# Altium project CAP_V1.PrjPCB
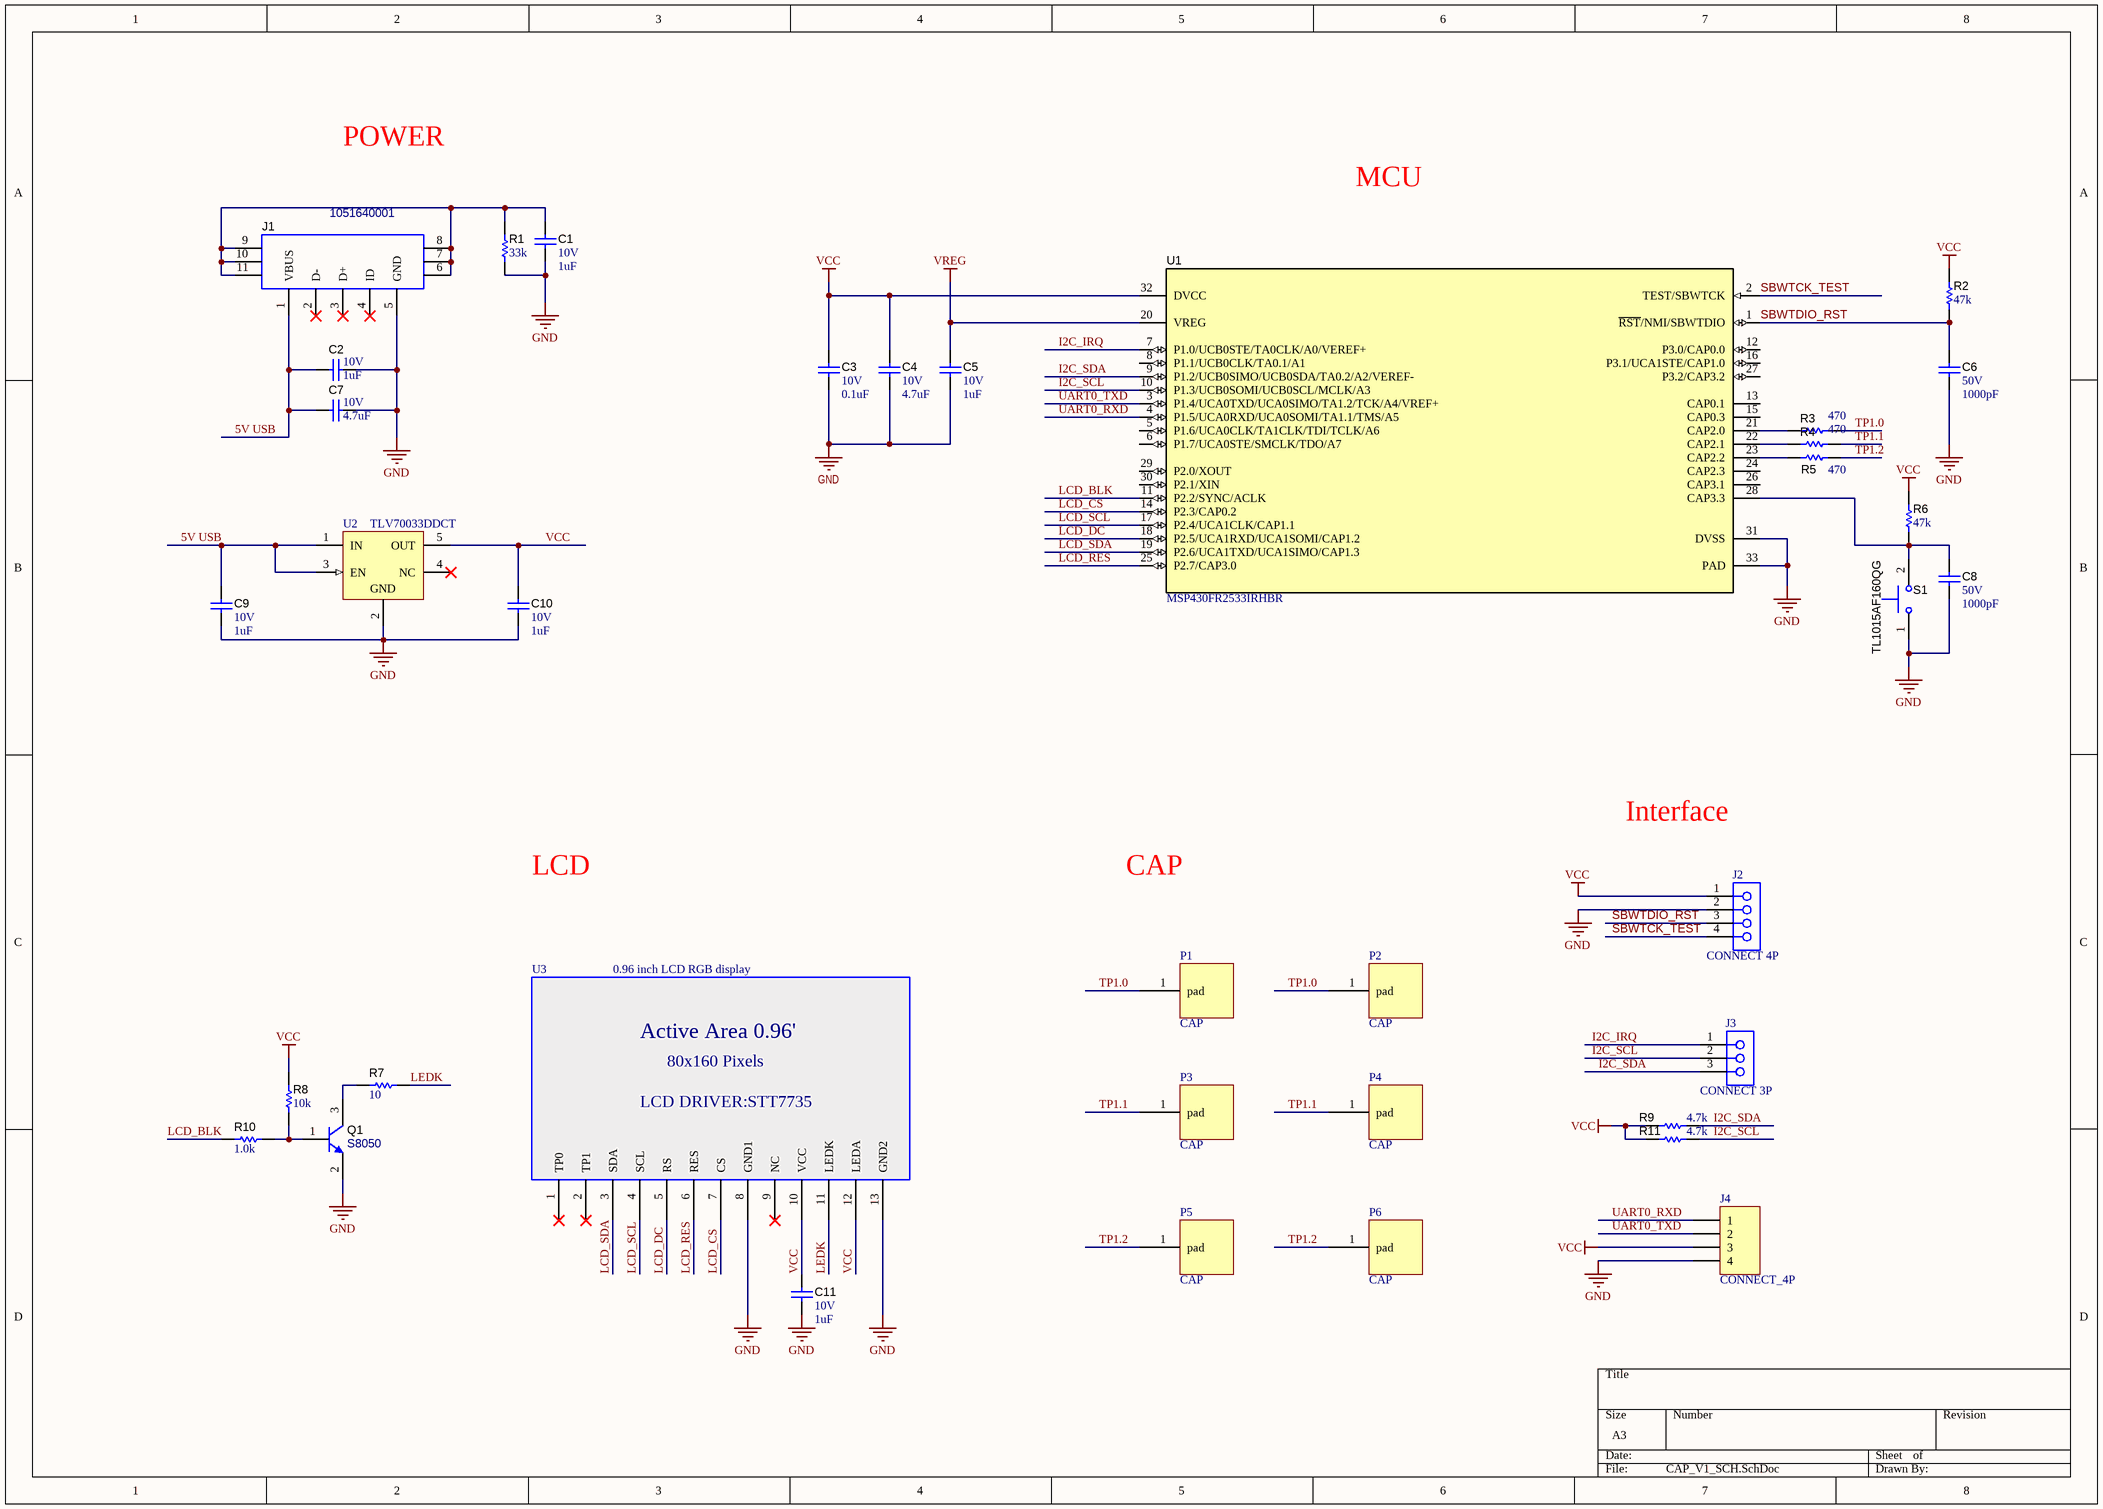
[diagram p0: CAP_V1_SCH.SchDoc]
1 sheet, 37 parts. Net scope: global (net labels, ports and power ports of the same name join across sheets).
Board file: CAP_V1_PCB.PcbDoc

## Sheet CAP_V1_SCH.SchDoc
size A3

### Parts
C1  VDC_V: 10V  ValueDisplayed: 1uF  [0603]  (hidden comment: CGB3B1X5R1A475K055AC)
C2  VDC_V: 10V  ValueDisplayed: 1uF  [0603]  (hidden comment: CGB3B1X5R1A475K055AC)
C3  VDC_V: 10V  ValueDisplayed: 0.1uF  [0603]  (hidden comment: CGB3B1X5R1A475K055AC)
C4  VDC_V: 10V  ValueDisplayed: 4.7uF  [0603]  (hidden comment: CGB3B1X5R1A475K055AC)
C5  VDC_V: 10V  ValueDisplayed: 1uF  [0603]  (hidden comment: C1608X5R1A105K080AC)
C6  VDC_V: 50V  ValueDisplayed: 1000pF  [0402]  (hidden comment: GRM155R61H102KA01D)
C7  VDC_V: 10V  ValueDisplayed: 4.7uF  [0603]  (hidden comment: CGB3B1X5R1A475K055AC)
C8  VDC_V: 50V  ValueDisplayed: 1000pF  [0402]  (hidden comment: GRM155R61H102KA01D)
C9  VDC_V: 10V  ValueDisplayed: 1uF  [0603]  (hidden comment: CGB3B1X5R1A475K055AC)
C10  VDC_V: 10V  ValueDisplayed: 1uF  [0603]  (hidden comment: CGB3B1X5R1A475K055AC)
C11  VDC_V: 10V  ValueDisplayed: 1uF  [0603]  (hidden comment: CGB3B1X5R1A475K055AC)
J1  1051640001  [Molex_1051640001]
J2  CONNECT 4P  [HDR1X4]
J3  CONNECT 3P  [HDR1X3]
J4  CONNECT_4P  [HDR1X4]
P1  CAP  [PCBComponent_1]
P2  CAP  [PCBComponent_1]
P3  CAP  [PCBComponent_1]
P4  CAP  [PCBComponent_1]
P5  CAP  [PCBComponent_1]
P6  CAP  [PCBComponent_1]
Q1  S8050  [SOT-23]
R1  ValueDisplayed: 33k  [0402]  (hidden comment: CRCW040247K0JNED)
R2  ValueDisplayed: 47k  [0402]  (hidden comment: CRCW040247K0JNED)
R3  ValueDisplayed: 470  [0402]  (hidden comment: CRCW040247K0JNED)
R4  ValueDisplayed: 470  [0402]  (hidden comment: CRCW040247K0JNED)
R5  ValueDisplayed: 470  [0402]  (hidden comment: CRCW040247K0JNED)
R6  ValueDisplayed: 47k  [0402]  (hidden comment: CRCW040247K0JNED)
R7  ValueDisplayed: 10  [0402L]  (hidden comment: CRCW040210R0JNED)
R8  ValueDisplayed: 10k  [0402L]  (hidden comment: CRCW040210K0JNED)
R9  ValueDisplayed: 4.7k  [0402]  (hidden comment: CRCW04024K70JNED)
R10  ValueDisplayed: 1.0k  [0402L]  (hidden comment: CRCW04021K00JNED)
R11  ValueDisplayed: 4.7k  [0402]  (hidden comment: CRCW04024K70JNED)
S1  TL1015AF160QG  [SW_TL1015AF160QG]
U1  MSP430FR2533IRHBR  [RHB0032E_NV]
U2  TLV70033DDCT  [DDC0005A_N]
U3  0.96 inch LCD RGB display  [GMT096-01]

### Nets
GND: C1.2 C2.2 C3.2 C4.2 C5.2 C6.2 C7.2 C8.2 C9.2 C10.2 C11.2 J1.5(GND) J2.2 J4.4 Q1.2(E) R1.1 S1.1 U1.31(DVSS) U1.33(PAD) U2.2(GND) U3.8(GND1) U3.13(GND2)
VCC: C3.1 C4.1 C10.1 C11.1 J2.1 J4.3 R2.2 R6.2 R8.2 R9.1 R11.1 U1.32(DVCC) U2.5(OUT) U3.10(VCC) U3.12(LEDA)
VREG: C5.1 U1.20(VREG)
5V USB: C2.1 C7.1 C9.1 J1.1(VBUS) U2.1(IN) U2.3(EN)
I2C_IRQ: J3.1 U1.7(P1.0/UCB0STE/TA0CLK/A0/VEREF+)
I2C_SCL: J3.2 R11.2 U1.10(P1.3/UCB0SOMI/UCB0SCL/MCLK/A3)
I2C_SDA: J3.3 R9.2 U1.9(P1.2/UCB0SIMO/UCB0SDA/TA0.2/A2/VEREF-)
LCD_BLK: R10.1 U1.11(P2.2/SYNC/ACLK)
LCD_CS: U1.14(P2.3/CAP0.2) U3.7(CS)
LCD_DC: U1.18(P2.5/UCA1RXD/UCA1SOMI/CAP1.2) U3.5(RS)
LCD_RES: U1.25(P2.7/CAP3.0) U3.6(RES)
LCD_SCL: U1.17(P2.4/UCA1CLK/CAP1.1) U3.4(SCL)
LCD_SDA: U1.19(P2.6/UCA1TXD/UCA1SIMO/CAP1.3) U3.3(SDA)
LEDK: R7.2 U3.11(LEDK)
SBWTCK_TEST: J2.4 U1.2(TEST/SBWTCK)
SBWTDIO_RST: C6.1 J2.3 R2.1 U1.1(~{RST}/NMI/SBWTDIO)
TP1.0: P1.1(pad) P2.1(pad) R3.1
TP1.1: P3.1(pad) P4.1(pad) R4.1
TP1.2: P5.1(pad) P6.1(pad) R5.1
UART0_RXD: J4.1 U1.4(P1.5/UCA0RXD/UCA0SOMI/TA1.1/TMS/A5)
UART0_TXD: J4.2 U1.3(P1.4/UCA0TXD/UCA0SIMO/TA1.2/TCK/A4/VREF+)
NetC1_1: C1.1 J1.6 J1.7 J1.8 J1.9 J1.10 J1.11 R1.2
NetC8_1: C8.1 R6.1 S1.2 U1.28(CAP3.3)
NetQ1_1: Q1.1(B) R8.1 R10.2
NetQ1_3: Q1.3(C) R7.1
NetR3_2: R3.2 U1.21(CAP2.0)
NetR4_2: R4.2 U1.22(CAP2.1)
NetR5_2: R5.2 U1.23(CAP2.2)

Not connected (* = marked no-connect by the designer): J1 2(D-)* 3(D+)* 4(ID)*; U1 5(P1.6/UCA0CLK/TA1CLK/TDI/TCLK/A6) 6(P1.7/UCA0STE/SMCLK/TDO/A7) 8(P1.1/UCB0CLK/TA0.1/A1) 12(P3.0/CAP0.0) 13(CAP0.1) 15(CAP0.3) 16(P3.1/UCA1STE/CAP1.0) 24(CAP2.3) 26(CAP3.1) 27(P3.2/CAP3.2) 29(P2.0/XOUT) 30(P2.1/XIN); U2 4(NC)*; U3 1(TP0)* 2(TP1)* 9(NC)*

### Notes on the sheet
- POWER
- MCU
- Interface
- LCD
- CAP

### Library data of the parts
C1-C4 C7 C9-C11 = CMP-0007105-2: CAP, CERM, 4.7 uF, 10 V, +/- 10%, X5R, 0603; Manufacturer: TDK; TaMin_C: -55°C; Polarized: N; SizeAreaWB_mm2: 4.68; Value1: Unknown; U/M: EA; Value: 4.7uF; TaMax_C: 85°C; SizeZ_mm: 1; SizeX_mm: 1.6; SizeY_mm: 0.8; SizeArea_mm2: 1.28; Cap_F: 4.7µF; AEC Category: Q200
C5 = CMP-0007002-5: CAP, CERM, 1 uF, 10 V, +/- 10%, X5R, 0603; Manufacturer: TDK; TaMin_C: -55°C; Polarized: N; SizeAreaWB_mm2: 4.68; Value1: Unknown; U/M: EA; Value: 1uF; TaMax_C: 85°C; SizeZ_mm: 1; SizeX_mm: 1.6; SizeY_mm: 0.8; SizeArea_mm2: 1.28; Cap_F: 1µF; AEC Category: Q200
C6 C8 = CMP-0006613-2: CAP, CERM, 1000 pF, 50 V, +/- 10%, X5R, 0402; Manufacturer: MuRata; TaMin_C: -55°C; Polarized: N; SizeAreaWB_mm2: 3; Value1: Unknown; U/M: EA; Value: 1000pF; TaMax_C: 85°C; SizeZ_mm: 0.6; SizeX_mm: 1; SizeY_mm: 0.5; Cap_F: 1nF; AEC Category: Q200
J1 = CMP-0055311-1: Receptacle, USB 2.0, Micro B, 5 Position, R/A, SMT; Manufacturer: Molex; CNHeader: FALSE; Current_A: 1.8A; Gender: Female; Voltage_V: 30V; Pitch_mm: 0.65; ContactFinish: Gold; CT: TRUE; Cert_UL: Y
J4 = Header 4: Header, 4-Pin
Q1 = CMP-0000378-2: Transistor, NPN, 30 V, 0.1 A, SOT-23; PartNumber: BC849CLT1G; Manufacturer: ON Semiconductor; TaMax_C: 150°C; Value2: 800; Value1: 0.1 A; Vcesat1_V: 700mV; SizeX_mm: 2.5; SizeY_mm: 3; TaMin_C: -55°C; IcRated_A: 100mA; CompType: BJT; SizeZ_mm: 1.1; Value: 30 V; SizeArea_mm2: 7.5; NPN: 1; Vceo_V: 30V; PNP: 0; AEC Category: Q101; SizeAreaWB_mm2: 14; U/M: EA
R1-R6 = CMP-0026935-3: RES, 47 k, 5%, 0.063 W, AEC-Q200 Grade 0, 0402; Manufacturer: Vishay-Dale; Power_W: 63mW; TempCo: 200 ppm/C; Value_Code: 47k0; Value: 47k; EIA_Code: E24; SizeX_mm: 1; SizeY_mm: 0.5; SizeZ_mm: 0.6; Value2: 0.063W; AEC Qualified: Y; VDC_V: 50V; AEC Category: Q200; AEC Grade: 0
R7 = CMP-0026827-3: RES, 10, 5%, 0.063 W, AEC-Q200 Grade 0, 0402; Manufacturer: Vishay-Dale; Power_W: 63mW; TempCo: 200 ppm/C; Value_Code: 10R0; Value: 10; EIA_Code: E24; SizeX_mm: 1; SizeY_mm: 0.5; SizeZ_mm: 0.6; Value2: 0.063W; AEC Qualified: Y; VDC_V: 50V; AEC Category: Q200; AEC Grade: 0
R8 = CMP-0026825-5: RES, 10 k, 5%, 0.063 W, AEC-Q200 Grade 0, 0402; Manufacturer: Vishay-Dale; Power_W: 63mW; TempCo: 200 ppm/C; Value_Code: 10k0; Value: 10k; EIA_Code: E24; SizeX_mm: 1; SizeY_mm: 0.5; SizeZ_mm: 0.6; Value2: 0.063W; AEC Qualified: Y; VDC_V: 50V; AEC Category: Q200; AEC Grade: 0
R9 R11 = CMP-0026938-5: RES, 4.7 k, 5%, 0.063 W, AEC-Q200 Grade 0, 0402; Manufacturer: Vishay-Dale; Power_W: 63mW; TempCo: 200 ppm/C; Value_Code: 4k70; Value: 4.7k; EIA_Code: E24; SizeX_mm: 1; SizeY_mm: 0.5; SizeZ_mm: 0.6; Value2: 0.063W; AEC Qualified: Y; VDC_V: 50V; AEC Category: Q200; AEC Grade: 0
R10 = CMP-0026852-3: RES, 1.0 k, 5%, 0.063 W, AEC-Q200 Grade 0, 0402; Manufacturer: Vishay-Dale; Power_W: 63mW; TempCo: 200 ppm/C; Value_Code: 1k00; Value: 1.0k; EIA_Code: E24; Res_ohm: 1k; SizeX_mm: 1; SizeY_mm: 0.5; SizeZ_mm: 0.6; Value2: 0.063W; AEC Qualified: Y; VDC_V: 50V; AEC Category: Q200; AEC Grade: 0
S1 = CMP-0002143-2: Switch, Tactile, SPST-NO, 0.05A, 12V, SMT; Manufacturer: E-Switch; SymbolCreator: a0412235; CurrentRating_mA: 50A; PositionCount: 1; SwitchFunction: Off-Mom
U1 = CMP-0076461-1: 16 MHz Ultra-Low-Power Microcontroller with 16 KB FRAM, CapTIvate touch technology, RHB0032E (VQFN-32); Manufacturer: Texas Instruments; Alternate PartNumber: MSP430FR2533IRHBT; SizeAreaWB_mm2: 49.0; SizeArea_mm2: 25.0; SizeZ_mm: 1.0; SizeY_mm: 5.0; U/M: EA; CompType: IC
U2 = CMP-0035824-1: Single Output LDO, 200 mA, Fixed 3.3 V Output, 2 to 5.5 V Input, with Low IQ, 5-pin SOT (DDC), -40 to 125 degC, Green (RoHS & no Sb/Br); Manufacturer: Texas Instruments; Iq(Typ)(mA): 0.03; Vin(Max)(V): 5.5; Iout(Max)(A): 0.2; Vout Adj(Min)(V): 3.3; SubFamily: Single Channel LDO; Accuracy(%): 2; Vdo(Typ)(mV): 175
U3 = GMT096-01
